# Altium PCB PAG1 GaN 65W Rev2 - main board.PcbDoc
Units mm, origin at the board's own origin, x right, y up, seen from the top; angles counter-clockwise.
Board outline 52 x 42 mm, 2 copper layers (Top Layer, Bottom Layer); 58 components, 37 nets, 153 pads, 55 vias.
Unrouted connection lines stored in the file: 1.
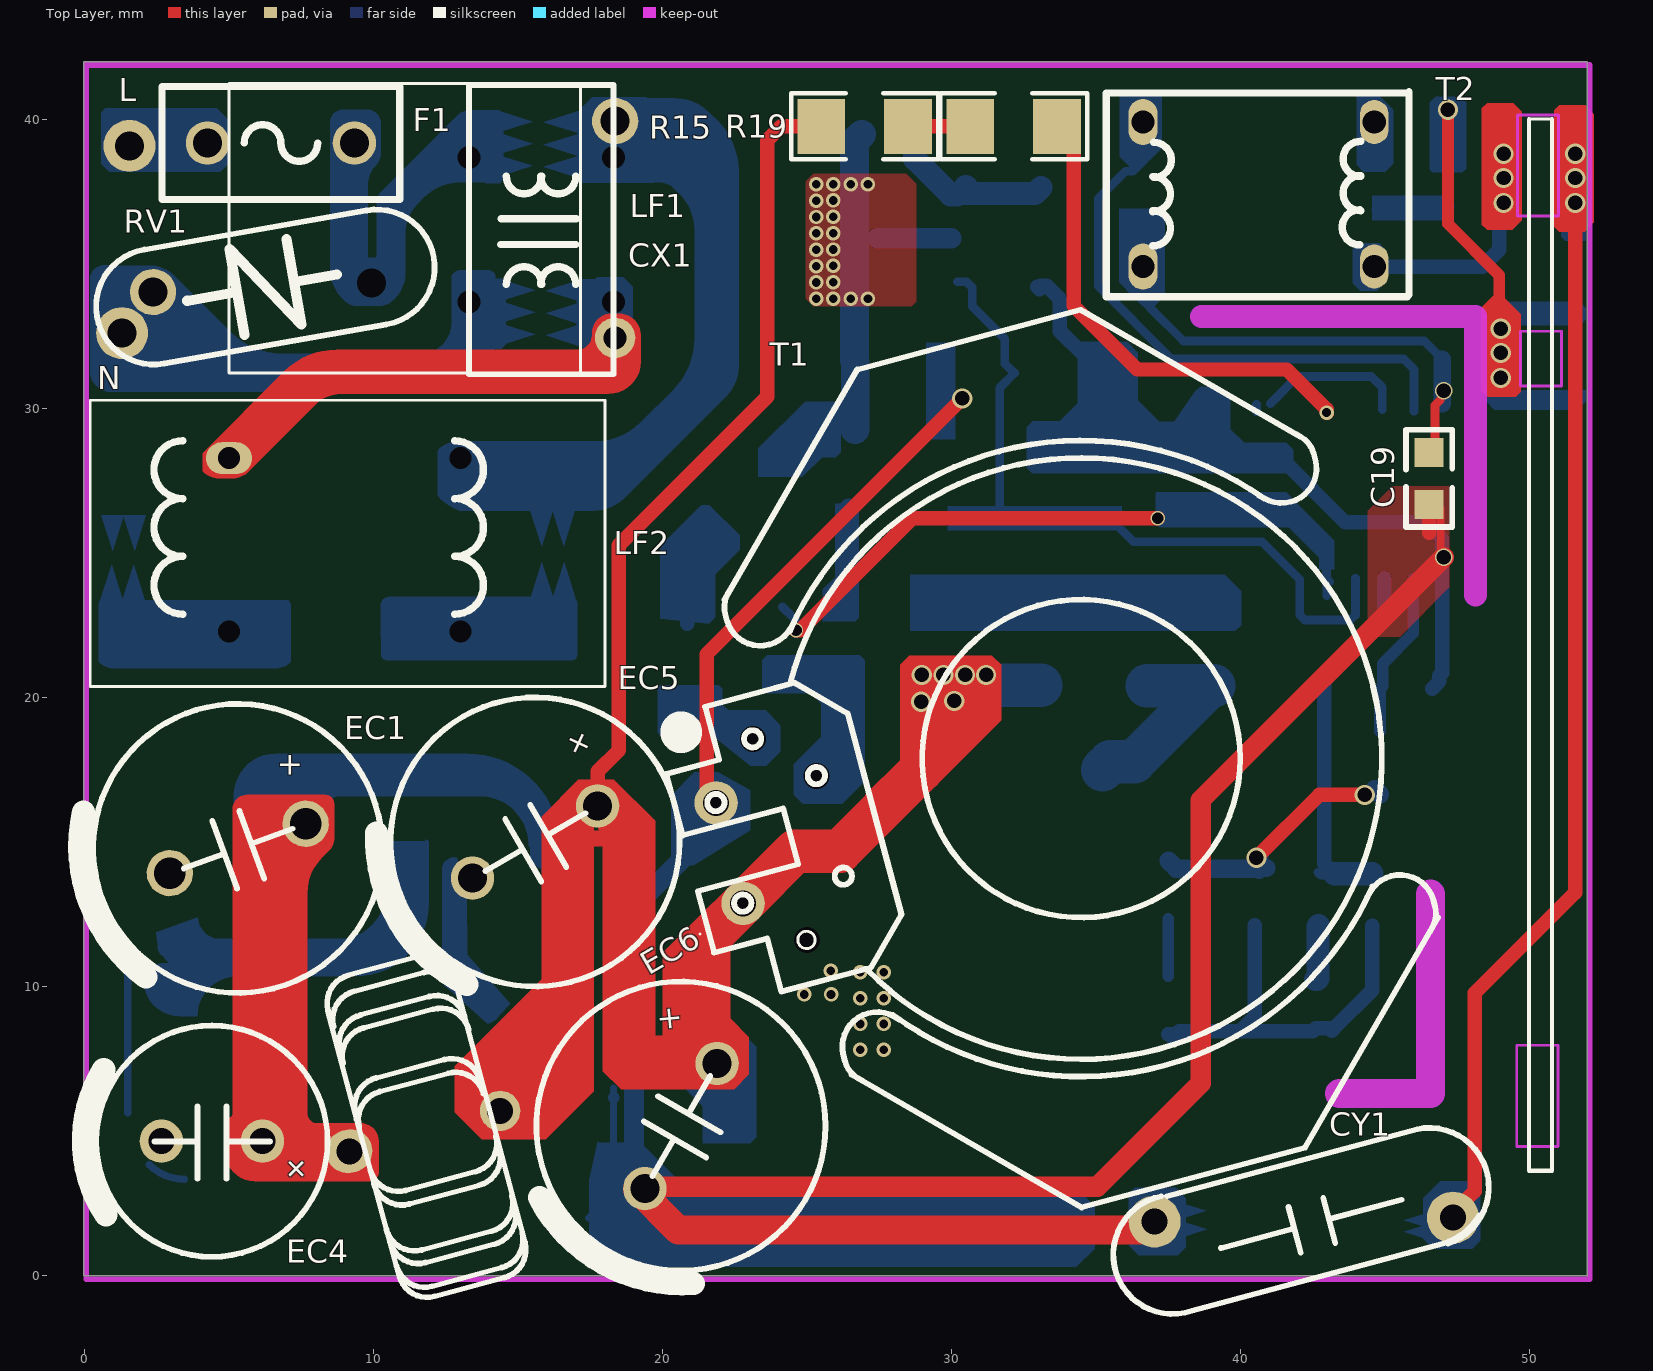
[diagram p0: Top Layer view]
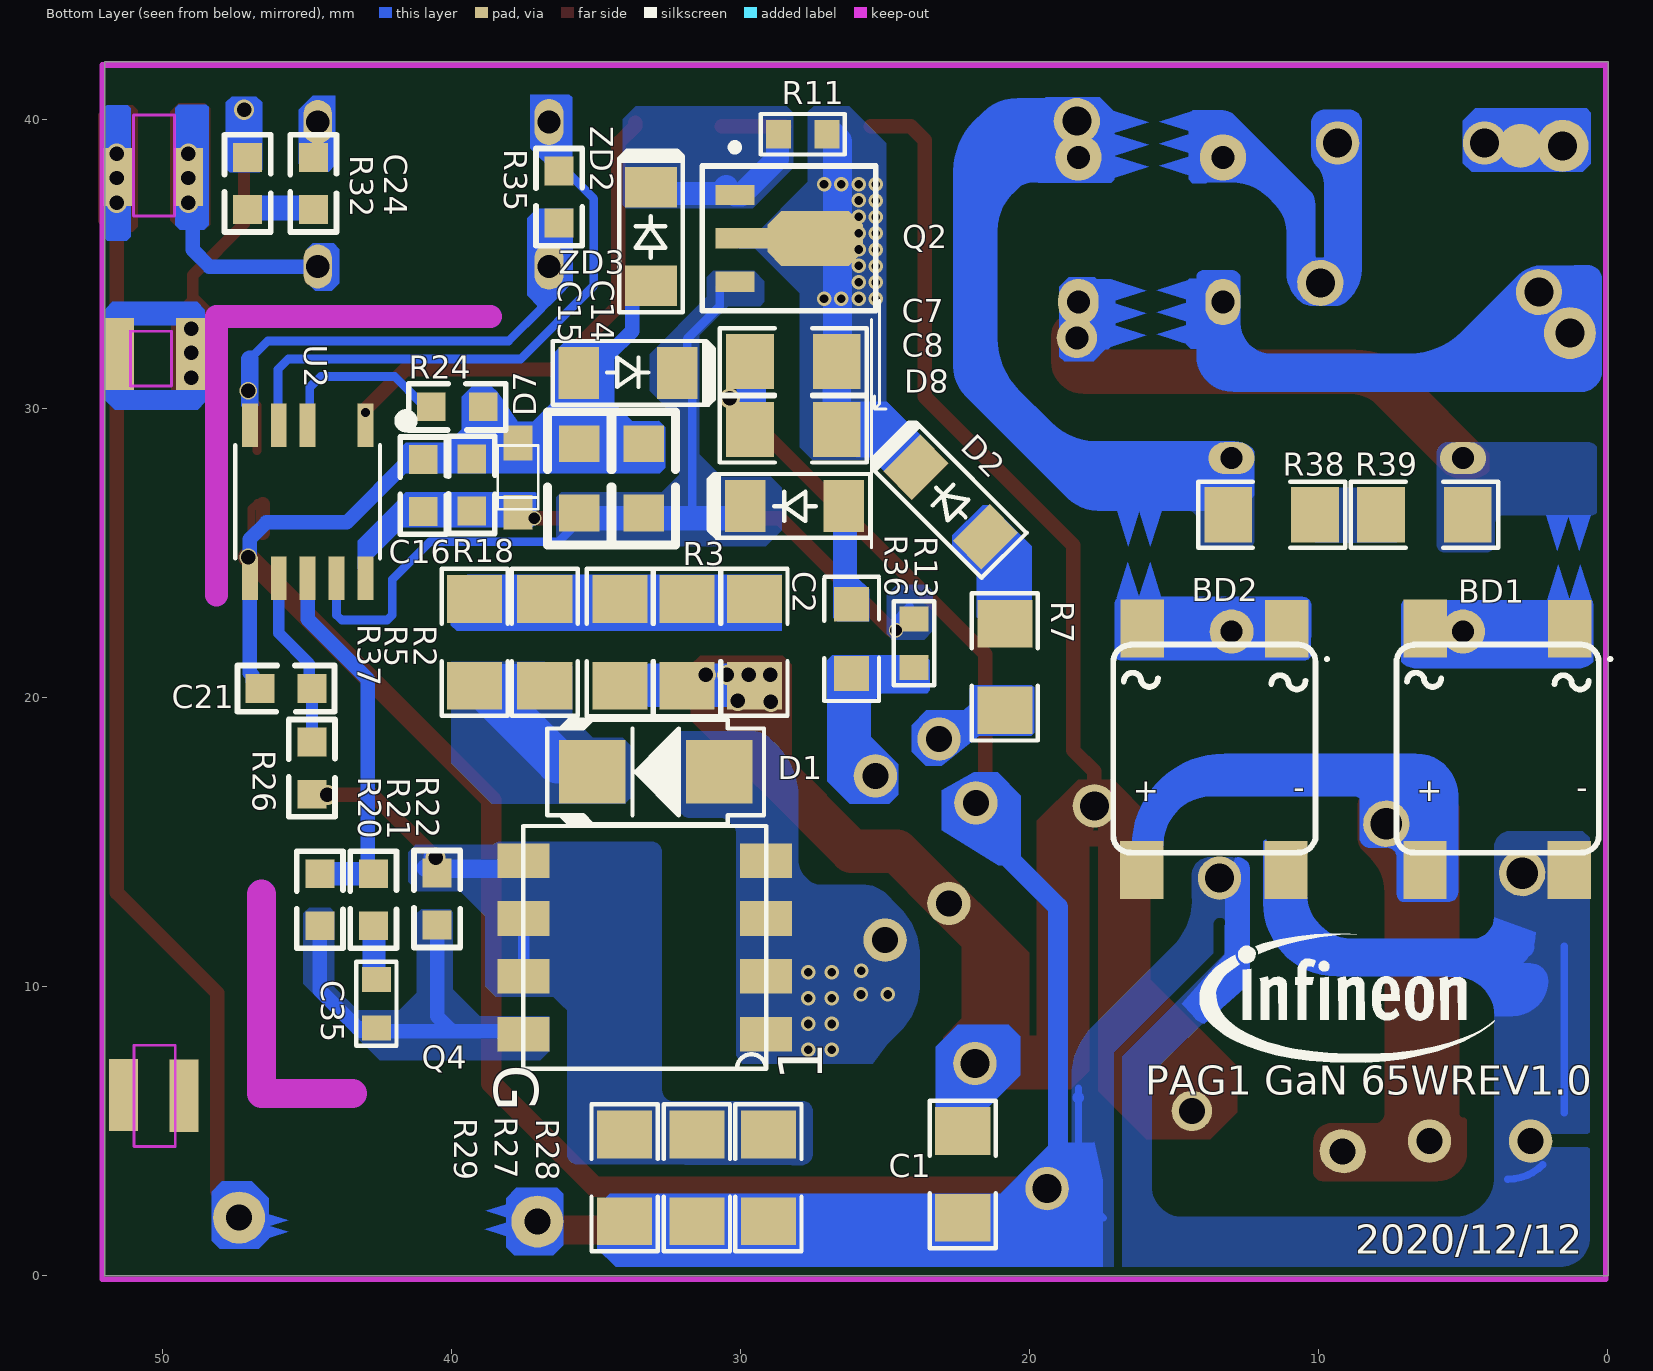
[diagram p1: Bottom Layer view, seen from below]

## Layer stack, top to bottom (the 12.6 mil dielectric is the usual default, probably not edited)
Top Solder: solder mask 0.0102, Solder Resist, Dk 3.5
Top Layer: signal copper 0.0356
Dielectric 1: dielectric 0.32, FR-4, Dk 4.8
Bottom Layer: signal copper 0.0356
Bottom Solder: solder mask 0.0102, Solder Resist, Dk 3.5

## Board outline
-0.02,-0.012 51.98,-0.012 51.98,41.988 -0.02,41.988

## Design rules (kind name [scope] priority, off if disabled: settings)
Clearance [All] p1: gap=0.254 ignorepadtopadclearanceinfootprint=FALSE except(0: Arc-Hole Track-Hole SMDPad-Hole THPad-Hole Via-Hole Fill-Hole Poly-Hole Region-Hole Text-Hole)
PolygonConnect [All] p1: connectstyle=Relief reliefconductorwidth=0.254 reliefentries=4 polygonreliefangle="90 Angle" airgapwidth=0.254
RoutingVias [All] p1: holewidth=0.711 width=1.27 viastyle="Through Hole" minholewidth=0.711 minwidth=1.27 maxholewidth=0.711 maxwidth=1.27
SolderMaskExpansion [All] p1: expansion=0.102 istentingtop=FALSE
Width [All] p1: maxlimit=0.254 minlimit=0.254 preferedwidth=0.254
30 further rules are at their usual default settings.

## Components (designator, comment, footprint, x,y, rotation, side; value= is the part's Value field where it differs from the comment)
BD1 "MSB407" BD(DB106) 3.813,18.223 r180 bottom
BD2 "MSB407" BD(DB106) 13.61,18.223 r180 bottom
C1 "103/500V 1206" R1206 22.313,4.998 r270 bottom
C2 "102/1KV 1206" R1206 29.52,20.398 r90 bottom
C7 "2.2UF 1206" R1206 26.67,31.617 r0 bottom
C8 "2.2UF 1206" r1206 26.667,29.265 r0 bottom
C14 "22UF/25V" WS0805 33.345,27.573 r90 bottom
C15 "22UF/25V" WS0805 35.577,27.573 r90 bottom
C16 "100PF" WS0603 40.97,27.323 r90 bottom
C19 "0.1UF" WS0603 46.52,27.573 r270 top
C21 "220PF" WS0603 45.72,20.298 r0 bottom
C24 "1nF  50V NPO" WS0603 44.77,37.773 r270 bottom
C35 "2.2nF/25V 0603" R0603 42.595,9.398 r270 bottom
CX1 "0.33uF" CX12.5 13.413,34.973 r270 top
CY1 "2200PF  400V" CAP10Y1 42.182,1.935 r15 top
D1 "GS2M  2A/1000V SMB" SMA 32.927,17.411 r0 bottom
D2 "DF1M" SOD-123/LL-34-T 22.72,26.748 r45 bottom
D7 "BAT54V2TA1G  SOD523" SOD-323-R 37.695,28.798 r270 bottom
D8 "DF1M" SOD-123/LL-34-T 28.12,26.623 r0 bottom
EC1 "33UF/400V" EC10#1 5.313,14.773 r200 top
EC4 "22UF400V" EC8-5_2 4.42,4.748 r180 top locked
EC5 "33UF400V" EC10#2 15.595,14.997 r210 top
EC6 "33UF400V" EC10#2 20.641,5.17 r240 top
F1 "T3.15A/250V" FUSE2 4.27,39.173 r0 top
LF1 "T9*3*3  600uH" T9*5*3 15.813,36.173 r270 top
LF2 "TD1212 15mH" "TD15 20*11" 8.013,25.873 r180 top locked
Q2 "FCX495QTA  NPN SOT89" SOT89 28.807,35.873 r270 bottom
Q4 "" DFN8*8_IGLD60R190D1 33.311,11.348 r90 bottom
R2 "390K 1206" R1206 34.17,23.398 r270 bottom
R3 "390K 1206" R1206 31.844,23.398 r270 bottom
R5 "10R/1206" R1206 36.77,20.398 r90 bottom
R7 "2.2R/1206" R1206 20.857,19.548 r90 bottom
R11 "200K" r0603 27.845,39.473 r0 bottom
R13 "7.5K" R0603 23.995,21.873 r90 bottom
R15 "47R 1206" R1206 25.495,39.748 r0 top
R18 "3k" WS0603 39.295,27.348 r90 bottom
R19 "47R 1206" R1206 30.645,39.748 r0 top
R20 "1K 0603" WS0603 44.545,12.998 r90 bottom
R21 "15R 0603" WS0603 42.695,12.998 r90 bottom
R22 "47K" WS0603 40.495,13.023 r270 bottom
R24 "499K" WS0603 39.795,30.048 r180 bottom
R26 "1K" WS0603 44.82,17.548 r270 bottom
R27 "0.43R 1206" r1206 31.509,1.881 r90 bottom
R28 "0.43R 1206" R1206 29.034,1.881 r90 bottom
R29 "0.43R 1206" R1206 34.009,1.881 r90 bottom
R32 "150R" WS0603 47.045,37.773 r270 bottom
R35 "2K" WS0603 36.27,37.298 r270 bottom
R36 "2.2R/0805" R0805 26.157,20.823 r90 bottom
R37 "10R/1206" R1206 39.195,20.398 r90 bottom
R38 "1.5M 1206" R1206 13.128,26.314 r180 bottom
R39 "1.5M 1206" R1206 7.845,26.314 r180 bottom
RV1 "10D561" MOV10D471 6.313,34.198 r10 top
T1 "RM10" RM10-3 34.495,17.873 r195 top locked
T2 "JQH LCL00T5138A1 3:9, 8mm" "Pulse Transformer" 40.62,37.398 r180 top
U2 "CYPAP112A3 SOIC10" SO-10 44.92,26.823 r270 bottom
ZD2 "16V" SOD-123/LL-34-T 33.095,35.923 r90 bottom
ZD3 "16V" SOD-123/LL-34-T 33.895,31.223 r180 bottom
? "T10" T11 11.78,4.998 r15 top

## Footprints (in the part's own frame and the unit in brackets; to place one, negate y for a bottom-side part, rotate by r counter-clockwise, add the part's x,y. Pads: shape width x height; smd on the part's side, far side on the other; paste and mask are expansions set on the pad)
BD(DB106) [mm]
  rect 1.5x2 smd: 1(2.48,-4.2) 2(2.5,4.15) 3(-2.5,4.16) 4(-2.51,-4.2)
  silkscreen extent -3.5,-3.6 3.9,3.6
CAP10Y1 [mm]
  round 1.8 hole 0.9: 1(-5,1.27) 2(5,-1.27)
  silkscreen extent -6.74,-2.09 6.54,2.06
CX12.5 [mm]
  round 1.6 hole 1: 1(-4.953,4.953)
  round 1.4 hole 0.8: 2(2.54,4.953)
  silkscreen extent -6.25,-8.4 3.75,3.75
DFN8*8_IGLD60R190D1 [mm]
  rect 1.2x1.8 smd: 1(-3,-4.191) 2(-1,-4.191) 3(1,-4.191) 4(3,-4.191) 5(3,4.191) 6(1,4.191) 7(-1,4.191) 8(-3,4.191)
  silkscreen extent -4.2,-4.2 4.2,4.2
EC8-5_2 [mm]
  round 1.5 hole 0.9: 1(-1.75,0.1) 2(1.75,0.1)
  silkscreen extent -4,-3.9 4.44,4.1
EC10#1 [mm]
  round 1.6 hole 1.1: 1(-2.5,0) 1(2.5,0)
  silkscreen extent -5,-5 5.44,5
EC10#2 [mm]
  round 1.5 hole 1: 1(-2.5,0) 2(2.5,0)
  silkscreen extent -5,-5 5.44,5
FUSE2 [mm]
  round 1.5 hole 1: 1(-0.005,-0.002) 2(5.075,-0.002)
  silkscreen extent -1.58,-1.96 6.65,1.95
MOV10D471 [mm]
  round 0 / inner round 0 / far side round 1.6 hole 1: 1(3.6,-0.5)
  round 1.6 hole 1: 2(-3.9,0.5)
  silkscreen extent -5.96,-2 5.87,2
"Pulse Transformer" [mm]
  oval 1x1.524 hole 0.8: 1(-4,-2.5) 2(-4,2.5)
  oval 1x1.6 hole 0.8: 3(4,-2.5) 4(4,2.5)
  silkscreen extent -5.2,-3.55 5.26,3.54
R0603 [mm]
  rect 0.87x1 smd: 1(-0.838,0) 2(0.84,0)
  silkscreen extent -1.45,-0.7 1.45,0.7
r0603 [mm]
  rect 0.87x1 smd: 1(-0.838,0) 2(0.84,0)
  silkscreen extent -1.45,-0.7 1.45,0.7
R0805 [mm]
  rect 1.2x1.2 smd: 1(0,0) 2(2.4,0)
  silkscreen extent -0.95,-0.95 3.35,0.95
R1206 [mil]
  rect 65x75 smd: 1(0,0) 2(118.11,0)
  silkscreen extent -41,-45 159,45
r1206 [mil]
  rect 65x75 smd: 1(0,0) 2(118.11,0)
  silkscreen extent -41,-45 159,45
RM10-3 [mm]
  round 1.5 hole 0.9: 1(12.6,-1.8) 6(12.6,1.8)
  round 0 / inner round 0 / far side round 1.5 hole 0.9: 2(10.8,-3.6) 3(9,-1.8) 5(10.8,3.6)
  silkscreen extent -10.49,-15.01 14.01,14.99
SMA [mm]
  rect 2.3x2.2 smd: A(-2.192,-0.009) K(2.208,-0.009)
  silkscreen extent -3.74,-1.81 3.76,1.79
SO-10 [mm]
  rect 1.5x0.55 smd: 1(-2.59,1.95) 3(-2.59,-0.05) 4(-2.59,-1.05) 5(-2.59,-2.05) 6(2.71,-2.05) 7(2.71,-1.05) 8(2.71,-0.05) 9(2.71,0.95) 10(2.71,1.95)
  silkscreen extent -2.94,-2.55 2.01,3.55
SOD-123/LL-34-T [mm]
  rect 1.4x1.8 smd: 1(-1.69,0) 2(1.71,0)
  silkscreen extent -2.6,-1.1 2.98,1.1, body extent -1.85,-0.81 1.85,0.79, height 1.2
SOD-323-R [mm]
  rect 1.2x1 smd: 1(0,0) 2(2.393,0)
  silkscreen extent 0.09,-0.7 2.29,0.7
SOT89 [mm]
  rect 0.7x1.35 smd: 1(-1.5,-1.388) 3(1.5,-1.388)
  rect 0.7x1.8 smd: 2(0,-1.162)
  oct 1.9x3.3 smd: 2(0,1.388)
  silkscreen extent -3.27,-2.51 2.5,3.49, body extent -2.2,-1.97 2.3,1.97, height 1.4
T9*5*3 [mm]
  round 0 / inner round 0 / far side round 1.6 hole 0.8: 1(-2.5,-2.5) 2(-2.5,2.5)
  round 0 / inner round 0 / far side oval 1.6x1.4 hole 0.8: 3(2.5,2.5)
  round 0 / inner round 0 / far side oval 1.6x1.2 hole 0.8: 4(2.5,-2.5)
  silkscreen extent -5,-2.5 5,2.5
T11 [mm]
  oval 1.6x1.5 hole 0.9: 1(-2.7,0)
  round 1.4 hole 0.9: 2(2.7,0)
  silkscreen extent -2.18,-5.61 2.39,5.89
"TD15 20*11" [mm]
  round 0 / inner round 0 / far side oval 1.6x1.1 hole 0.762: 1(-5,-2.4)
  round 0 / inner round 0 / far side round 1.524 hole 0.762: 2(-5,3.6) 3(3,3.6)
  oval 1.6x1.1 hole 0.762: 4(3,-2.4)
  silkscreen extent -10,-4.4 7.8,5.5
WS0603 [mm]
  rect 1x1 smd: 1(-0.9,0) 2(0.9,0)
  silkscreen extent -1.68,-0.8 1.68,0.8, body extent -1.78,-0.9 1.78,0.9, height 1.27
WS0805 [mm]
  rect 1.27x1.397 smd: 1(-1.2,0) 2(1.2,0)
  silkscreen extent -2.3,-1.1 2.3,1.1, body extent -2.45,-1.25 2.45,1.25, height 0.4

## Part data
BD1 BD2: library part BR805D_1
C1 C2 C7 C8 C14 C15 C16 C19 C21 C24 C35 CX1: library part CAP1, "电容"
CY1: library part 0_0.01uF-50V-10%-X7R-0603
D1 D2 D7 D8: library part DIODE, "二极管"
EC1 EC4 EC5 EC6: library part CAP2, "电解电容"
F1: library part FUSE1
LF1 LF2: library part "INDUCTOR IRON_8"
Q2: library part NPN
Q4: library part IGT60R190D1S, "Cool GaN PG-LSON-8"
R2 R3 R5 R7 R11 R13 R15 R18 R19 R20 R21 R22 R24 R26 R27 R28 R29 R32 R35 R36 R37 R38 R39: library part RES2, "电阻"
RV1: library part VARISTOR
T1: library part PA5222NL_24
T2: library part TRANSFORMER_11
U2: library part PAG1P_3
ZD2 ZD3: library part ZD1
?: library part INDUCTOR, "电感"

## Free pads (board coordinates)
  rect 1x2.5 smd far side: 0(49.02,31.873) 0(49.245,6.223) 0(51.345,6.248) 0(51.47,31.873)
  rect 1x2 smd far side: 0(49.095,37.998) 0(51.545,37.998)
  round 1.524 smd far side: 1(3.02,39.073)
  round 1.8 hole 1: L(1.57,39.073) N(1.313,32.598)

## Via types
v1: diameter 0.5, hole 0.3, Top Layer to Bottom Layer, 32 vias
v2: diameter 0.7, hole 0.5, Top Layer to Bottom Layer, 19 vias
v3: diameter 0.5, hole 0.4, Top Layer to Bottom Layer, 2 vias
v4: diameter 0.6, hole 0.5, Top Layer to Bottom Layer, 2 vias

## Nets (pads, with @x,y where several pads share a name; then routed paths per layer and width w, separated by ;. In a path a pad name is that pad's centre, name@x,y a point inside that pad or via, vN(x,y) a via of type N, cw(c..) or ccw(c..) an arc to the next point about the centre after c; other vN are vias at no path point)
GND: BD1.1 BD2.1 C1.2 C7.2 C8.2 C14.2 C15.2 C16.2 C19.2 C21.2 CY1.1 D7.1 EC1.1@2.964,13.918 EC4.2 EC5.2 EC6.2 R18.2 R24.2 R27.1 R28.1 R29.1 T1.1 U2.6 ZD2.1 ZD3.1 | length 154.7
  Top Layer w0.254: EC6.2@18.87,2.998 EC6.2@18.905,3.333 ; C19.2@46.72,26.723 46.92,26.523 v4@46.92,24.848
  Top Layer w0.5: EC5.2@13.348,13.523 EC5.2@13.545,13.72 ; T1.1 21.531,16.678 21.531,21.497 v2(30.37,30.336)
  Top Layer w0.508: 46.52,25.698 C19.2 ; v4@46.92,24.848 v4(47.02,24.848)
  Top Layer w0.7: EC6.2@19.27,3.198 19.4,3.068 35.04,3.068 38.62,6.648 38.62,16.448 v4(47.02,24.848)
  Top Layer w1: EC6.2@19.13,2.998 20.555,1.573 CY1.1@36.516,1.573
  Bottom Layer w0.254: 1.513,5.628 1.513,11.384 ; 2.257,3.832 ccw(c3.462,5.036) 3.462,3.333 ; BD2.1@10.933,13.973 11.13,13.776 BD2.1@11.558,13.348 ; EC5.2@13.305,13.348 EC5.2@13.348,13.523 ; 17.454,1.992 EC6.2@18.795,3.333 ; 18.31,4.223 18.31,6.148 18.31,6.487 ; EC6.2@18.97,2.998 20.045,2.998 19.02,4.023 ; C1.2@22.77,2.198 33.02,2.198
  Bottom Layer w0.4: 18.31,6.148 18.32,6.158
  Bottom Layer w0.5: 2.795,11.348 ccw(c2.895,11.348) 2.895,11.248 8.59,11.248 ccw(c8.59,13.788) 11.13,13.776 ccw(c8.59,13.788) 11.13,13.788 BD2.1 ; C14.2@33.302,28.448 35.577,28.448 D7.1@37.545,28.448 ; D7.1@37.708,28.61 38.07,28.248 R18.2@39.445,28.248 ; R24.2@39.37,30.073 39.37,28.323 R18.2@39.445,28.248 ; C21.2 46.87,20.548 46.87,20.741 46.97,20.841 U2.6 46.97,24.848 46.97,25.473 46.395,26.048 43.62,26.048 41.42,28.248 40.97,28.248 R18.2@39.445,28.248
  Bottom Layer w0.508: ZD2.1@32.965,34.203 33.045,34.123 33.045,34.183 ZD2.1 33.295,34.233 33.741,33.787 33.741,32.669 34.548,31.862
  Bottom Layer w0.7: 19.02,4.023 19.02,12.748 21.527,15.255
Net_1: ?.1 BD1.4 BD2.4 EC1.1@7.662,15.628 EC4.1 | length 15
  Bottom Layer w0.25: BD2.4@15.923,13.973 BD2.4@15.923,14.557 ; BD1.4 6.323,14.335 BD1.4
  Bottom Layer w1: BD1.4 6.323,15.149 cw(c8.863,15.149) 7.067,16.945 cw(c8.402,15.61) 8.402,17.498 13.18,17.498 cw(c13.18,15.108) 14.87,16.798 15.179,16.489 cw(c13.383,14.693) 15.923,14.693 BD2.4@15.923,14.557
NetBD1_2: BD1.2 BD1.3 LF2.3
NetBD2_2: BD2.2 BD2.3 LF2.2
NetC2_2: C2.2 R2.1 R3.1 R5.2 R37.2
NetC7_1: C7.1 C8.1 D2.2 Q2.2 R11.1 | length 12.9
  Bottom Layer w0.7: Q2.2@27.42,35.873 Q2.2@29.995,35.873
  Bottom Layer w1: C8.1 26.67,29.267 C7.1 26.645,31.642 26.645,39.223 R11.1@26.895,39.473
  other v1: 25.318,33.782 25.914,33.782 26.511,33.782 27.108,33.782 25.318,34.348 25.914,34.355 25.318,34.914 25.914,34.921 25.318,35.48 25.914,35.487 25.318,36.046 25.914,36.053 25.318,36.612 25.914,36.62 25.318,37.178 25.914,37.186 25.318,37.744 25.914,37.744 26.511,37.744 27.108,37.744
NetC14_1: C14.1 C15.1 D8.2 Q2.3 U2.9 ZD3.2 | length 21.4
  Bottom Layer w0.3: Q2.3 30.52,34.373 30.72,34.173 30.72,33.523 31.845,32.398 31.845,31.548 ZD3.2@32.095,31.298 ; 31.595,26.198 31.595,26.373 31.67,26.373 31.67,30.708 ZD3.2@32.177,31.215 ; C15.1@35.477,26.198 36.295,25.38 40.738,25.38 42.045,24.073 42.045,22.849 42.221,22.673 43.794,22.673 43.97,22.849 U2.9
NetC16_1: C16.1 D7.2 R13.2 R18.1 U2.10 | length 21.5
  Top Layer w0.5: v3(24.62,22.323) 24.77,22.323 28.645,26.198 v3(37.132,26.198)
  Bottom Layer w0.3: R13.2@24.145,23.135 24.57,22.71 ; v3(24.62,22.323) 24.62,22.66 24.57,22.71 ; D7.2@37.545,26.055 D7.2@37.813,26.323 ; C16.1@41.145,26.448 41.745,26.448 42.97,25.223 U2.10 ; U2.10@43.02,24.048 U2.10@43.02,24.038 ; R13.2@24.313,22.966 24.57,22.71 ; R13.2@24.313,22.966 24.57,22.71 ; R13.2@24.313,22.966 24.57,22.71 ; U2.10 43.07,23.998 U2.10@42.982,23.998 ; U2.10 42.972,23.996 42.982,23.523 U2.10@42.982,23.998 ; U2.10 U2.10@43.02,24.038 ; U2.10@42.982,23.998 43.02,24.035 U2.10@43.02,24.038
NetC19_1: C19.1 R35.2 T2.4 U2.5 | length 17.4
  Top Layer w0.3: C19.1@46.72,28.523 46.72,30.098 46.895,30.273
  Bottom Layer w0.3: R35.2 36.27,35.748 36.895,35.123 36.895,33.448 38.02,32.323 46.345,32.323 46.97,31.698
  Bottom Layer w0.6: U2.5@46.97,30.148 46.97,31.698
  other v4: 47.02,30.598
NetC21_1: C21.1 R26.1 U2.7 | length 5.8
  Bottom Layer w0.4: R26.1@44.82,18.819 C21.1 44.911,20.389 44.911,21.164 45.97,22.223 U2.7
NetC24_1: C24.1 T2.1 | length 1
  Bottom Layer w0.3: C24.1@44.62,38.898 T2.1
NetC24_2: C24.2 R32.2 | length 2.4
  Bottom Layer w0.5: C24.2 R32.2 R32.2@47.145,36.973
NetC35_1: C35.1 R21.1 | length 1.9
  Bottom Layer w0.8: C35.1 42.635,10.236 42.67,10.271 42.67,12.073 R21.1
NetC35_2: C35.2 Q4.8 R20.1 R22.2 | length 14
  Bottom Layer w0.5: Q4.8 Q4.8@37.77,8.348 ; Q4.8@37.645,8.223 Q4.8@37.77,8.348 ; 40.045,8.523 40.495,8.973 R22.2 ; 43.145,8.473 43.23,8.558 ; R20.1 44.545,9.873 43.23,8.558 ; Q4.8@37.77,8.348 37.875,8.453 42.49,8.453 C35.2 43.23,8.558
NetCX1_1: CX1.1 LF1.2 LF2.1 R38.1 | length 6.2
  Bottom Layer w1.5: 19.47,39.587 21.114,37.943 cw(c19.318,36.147) 21.858,36.147 21.858,34.256
NetCX1_2: CX1.2 LF1.3 LF2.4 R39.2
NetD1_A: D1.A Q4.1 Q4.2 Q4.3 Q4.4 T1.5
  other v1: 26.845,7.81 27.653,7.81 26.845,8.703 27.653,8.703 26.845,9.595 27.653,9.595 24.901,9.723 25.833,9.723 26.845,10.487 27.653,10.487 25.82,10.548
NetD1_K: D1.K R5.1 R37.1 | length 7.2
  Bottom Layer w1.5: D1.K@35.22,17.498 35.491,17.769 36.314,17.769 R37.1@38.943,20.398 ; R5.1 R37.1@38.943,20.398 ; R37.1@39.07,20.398 38.945,20.398 R37.1@38.943,20.398
NetD2_1: D2.1 R7.2 | length 2.8
  Bottom Layer w0.5: R7.2 20.857,23.775 D2.1@21.991,24.908
NetD3_2: 
NetD8_1: D8.1 R36.2 | length 3.5
  Bottom Layer w0.5: R36.2 26.245,23.31 26.245,26.438 D8.1
NetF1_1: F1.1 pad.1 pad.L | length 2.7
  Bottom Layer w0.3: pad.L 4.168,39.073 F1.1
NetF1_2: F1.2 LF1.1 RV1.1
NetGPIO1_1: R32.1 | length 10.2
  Top Layer w0.3: v2@49.195,31.91 v2@49.195,31.923
  Top Layer w0.4: v2(47.17,40.323) 47.17,36.373 48.945,34.598 48.945,31.098 v2(48.995,31.048)
  Bottom Layer w0.5: v2@48.97,31.923 48.945,31.923 v2@49.02,31.873
  other v2: 48.995,31.91 48.995,32.748
NetLF1_4: LF1.4 pad.N RV1.2
NetQ2_1: Q2.1 R11.2 ZD2.2 | length 5.6
  Bottom Layer w0.8: R11.2@28.695,39.498 28.72,39.473 28.72,38.623 29.97,37.373 Q2.1 ; Q2.1@30.47,37.423 32.885,37.423 ZD2.2 ; Q2.1@30.49,37.668 Q2.1@30.525,37.633
NetQ4_5: Q4.5 Q4.6 Q4.7 R22.1 R26.2 R27.2 R28.2 R29.2 | length 11
  Top Layer w0.5: v2(40.545,14.448) 42.72,16.623 44.27,16.623 v2@44.295,16.648
  Bottom Layer w0.4: Q4.7 Q4.6
  Bottom Layer w0.5: R22.1@40.645,13.973 40.72,14.048 40.72,14.098 v2@40.72,14.498
  Bottom Layer w0.635: Q4.5 37.777,14.073 R22.1@40.67,14.073 ; R22.1@40.67,14.098 40.72,14.098 R22.1@40.895,14.098 ; R26.2@44.638,16.83 R26.2
  other v2: 44.295,16.623
NetR7_1: R7.1 T1.2
NetR13_1: R13.1 R36.1 T1.3
NetR15_2: R15.2 R19.1 | length 2.2
  Top Layer w0.508: R15.2 R19.1
NetR19_2: R19.2 U2.1 | length 16.9
  Top Layer w0.5: R19.2@33.645,39.875 R19.2 34.22,39.173 34.22,36.823 34.22,33.537 36.42,31.337 41.596,31.337 42.97,29.963 v1(42.97,29.848)
NetR20_2: R20.2 R21.2 U2.8 | length 12.8
  Bottom Layer w0.305: R21.2@42.67,13.948 42.695,13.923 42.77,13.848 R21.2@42.87,13.848
  Bottom Layer w0.5: 43.245,13.898 42.895,14.248 42.895,20.623 44.97,22.698 U2.8
  Bottom Layer w0.8: 43.245,13.898 R20.2
NetR24_1: R24.1 U2.3 | length 5.5
  Bottom Layer w0.3: R24.1@40.545,29.873 R24.1@40.545,30.132 ; R24.1@41.02,30.157 41.961,31.098 44.52,31.098 44.895,30.723 U2.3@44.895,29.948
NetR35_1: R35.1 T2.3 U2.4 | length 20.2
  Bottom Layer w0.3: 37.12,39.898 37.12,39.048 R35.1 36.02,38.198 35.07,37.248 35.07,34.231 37.603,31.698 45.645,31.698 45.995,31.348 U2.4@45.995,29.898
NetR38_2: R38.2 R39.1
SR_VSS: CY1.2 pad.0@49.095,37.998 pad.0@51.545,37.998 T2.2 | length 45.9
  Top Layer w0.3: v2@49.295,37.96 v2@49.295,37.973 ; v2(51.57,37.098) v2(51.57,37.96) 51.57,38.598 v2@51.67,38.698 ; v2(51.57,38.798) 51.779,38.798 v2@51.779,38.796 ; v2@51.77,37.96 v2@51.77,37.973
  Top Layer w0.5: CY1.2@47.225,1.961 47.225,2.053 48.095,2.923 48.095,9.773 51.57,13.248 v2(51.57,37.098)
  Bottom Layer w0.5: T2.2@44.37,34.898 48.37,34.898 48.945,35.473 pad.0@48.945,37.643 ; pad.0@49.045,37.973 pad.0@49.07,37.973 ; pad.0@51.545,37.973 51.52,37.973 pad.0@51.545,37.998
  other v2: 49.095,37.098 49.095,37.96 49.095,38.798
"VDC IN": ?.2 C1.1 C2.1 EC5.1 EC6.1 R2.2 R3.2 R15.1 T1.6 | length 48.3
  Top Layer w0.5: EC5.1 17.76,17.436 18.485,18.161 18.485,25.263 23.62,30.398 23.62,39.262 24.106,39.748 R15.1
  Top Layer w1.5: EC6.1@21.405,7.663 21.405,11.488 T1.6 24.59,14.673 26.145,14.673 28.97,17.498 v2@28.97,20.673
  Bottom Layer w1.5: C2.1@29.37,20.414 29.72,20.414 33.095,20.414
  other v2: 28.945,19.848 30.095,19.873 28.97,20.773 29.72,20.773 30.47,20.773 31.195,20.773

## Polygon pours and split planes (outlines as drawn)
no net on Bottom Solder "NONET_L-01_P-001" (solid): 30.164,7.515 cw(c29.551,8.128) 29.551,7.261 25.592,7.261 cw(c25.592,7.568) 25.375,7.351 24.195,8.531 cw(c25.115,9.451) 23.814,9.451 23.814,11.833 cw(c24.734,11.833) 24.083,12.483 25.084,13.484 cw(c25.391,13.177) 25.391,13.611 27.497,13.611 27.825,13.939 ccw(c27.392,14.373) 28.005,14.373 28.005,15.336 cw(c28.439,15.336) 28.132,15.643 28.333,15.844 cw(c28.767,15.411) 28.767,16.024 29.678,16.024 cw(c29.678,15.157) 30.291,15.77 cw(c29.984,15.463) 30.418,15.463 30.418,8.128 cw(c29.551,8.128)
no net on Bottom Solder "NONET_L-01_P-001" (solid): 13.245,37.723 13.245,40.548 17.945,40.548 17.945,37.723
no net on Bottom Solder "NONET_L-01_P-001" (solid): 13.42,32.048 13.42,34.798 18.195,34.798 18.195,32.048
no net on Bottom Solder "NONET_L-01_P-001" (solid): 0.37,23.548 0.37,26.498 2.295,26.498 2.295,23.523
no net on Bottom Solder "NONET_L-01_P-001" (solid): 37.342,0.869 37.342,2.548 47.141,2.548 47.141,0.928
no net on Bottom Solder "NONET_L-01_P-001" (solid): 15.167,23.573 15.167,26.573 17.067,26.573 17.067,23.573
no net on Bottom Solder (solid): 19.907,21.717 19.907,25.222 21.381,26.695 21.635,26.695 22.701,25.629 22.701,25.07 21.863,24.232 21.863,21.717
no net on Bottom Solder (solid): 27.477,40.462 27.705,40.234 27.705,37.846 28.67,36.881 28.67,34.595 28.01,33.934 28.01,28.626 27.527,28.143 25.495,28.143 24.175,26.822 23.946,26.822 22.803,27.965 22.803,28.143 24.911,30.251 24.911,39.167 26.207,40.462
no net on Top Solder (solid): 25.013,38.075 24.759,37.821 24.759,33.579 25.013,33.325 28.493,33.325 28.747,33.579 28.747,37.795 28.467,38.075
NetCX1_1 on Bottom Layer "NETCX1_1_L02_P014" (solid, pour order 14): 12.226,27.074 12.226,25.411 ccw(c12.44,25.411) 12.44,25.197 14.04,25.197 ccw(c14.04,25.375) 14.218,25.375 14.218,26.179 cw(c14.487,26.179) 14.487,26.448 ccw(c14.487,26.56) 14.599,26.56 14.599,27.051
NetCX1_2 on Bottom Layer "NETCX1_2_L02_P013" (solid, pour order 13): 5.912,26.543 5.912,25.273 cw(c5.658,25.273) 5.658,25.019 4.185,25.019 cw(c4.185,25.298) 3.905,25.298 3.905,26.035 ccw(c3.651,26.035) 3.651,26.289 cw(c3.651,26.416) 3.524,26.416 3.524,26.543
NetR38_2 on Bottom Layer "NETR38_2_L02_P012" (solid, pour order 12): 7.309,27.254 7.309,25.349 10.128,25.349 10.128,27.254
NetCX1_2 on Bottom Layer "NETCX1_2_L02_P011" (solid, pour order 11): 0.324,28.448 cw(c0.705,28.448) 0.705,28.829 5.531,28.829 cw(c5.531,28.448) 5.912,28.448 5.912,26.543 cw(c5.658,26.543) 5.658,26.289 0.578,26.289 cw(c0.578,26.543) 0.324,26.543
NetC35_2 on Bottom Layer "NETC35_2_L02_P010" (solid, remove dead copper, pour order 10): 39.02,8.973 39.945,9.898 39.945,12.573 40.045,12.673 41.045,12.673 41.195,12.523 41.195,9.773 41.795,9.173 43.245,9.173 44.045,9.973 44.045,12.573 44.195,12.723 44.92,12.723 45.12,12.523 45.12,10.098 42.47,7.448 36.92,7.448 36.595,7.773 36.62,7.798 36.62,8.973
NetQ4_5 on Bottom Layer "NETQ4_5_L02_P009" (solid, remove dead copper, pour order 9): 37.02,14.948 37.07,14.898 41.27,14.898 41.27,14.873 41.495,14.648 41.495,13.623 41.17,13.298 39.695,13.298 38.82,12.423 38.82,9.998 38.47,9.648 36.47,9.648 35.72,8.898 33.62,8.898 32.845,9.673 32.845,14.423 33.395,14.973
NetC16_1 on Bottom Layer "NETC16_1_L02_P007" (solid, remove dead copper, pour order 7): 24.595,23.898 24.945,23.548 24.945,22.198 24.745,21.998 23.645,21.998 23.345,22.298 23.345,23.673 23.57,23.898
NetC14_1 on Bottom Layer "NETC14_1_L02_P006" (solid, remove dead copper, pour order 6): 30.945,34.748 31.17,34.523 31.17,33.848 33.145,31.873 33.145,30.598 32.12,29.573 32.12,27.698 32.72,27.098 36.195,27.098 36.37,26.923 36.37,25.248 36.345,25.223 29.12,25.223 28.57,25.773 28.57,27.248 28.945,27.623 30.645,27.623 31.42,28.398 31.42,32.523 30.42,33.523 29.32,33.523 29.17,33.673 29.17,34.398 29.52,34.748
NetC7_1 on Bottom Layer "NETC7_1_L02_P005" (solid, remove dead copper, pour order 5): 27.47,40.448 27.67,40.248 27.67,37.823 29.545,35.948 29.545,35.573 27.945,33.973 27.945,28.648 27.52,28.223 24.645,28.223 24.22,28.648 24.22,29.498 24.962,30.24 24.962,39.165 26.245,40.448
NetQ2_1 on Bottom Layer "NETQ2_1_L02_P004" (solid, remove dead copper, pour order 4): 33.62,40.448 34.07,39.998 34.07,37.023 33.97,36.923 29.57,36.923 28.17,38.323 28.17,40.223 28.395,40.448
NetD1_K on Bottom Layer "NETD1_K_L02_P003" (solid, remove dead copper, pour order 3): 36.77,21.223 39.995,21.223 39.995,17.723 38.595,16.323 33.97,16.323 33.97,16.348 33.745,16.573 33.745,18.273 34.07,18.598 35.12,18.598 35.12,18.623 35.82,19.323 35.82,21.098 35.945,21.223
NetQ4_5 on Bottom Layer "NETQ4_5_L02_P002" (solid, pour order 2): 28.22,3.823 27.92,3.823 cw(c27.92,4.248) 27.495,4.248 27.495,5.673 cw(c27.845,5.673) 27.845,6.023 32.32,6.023 ccw(c32.32,6.423) 32.72,6.423 32.72,14.648 cw(c33.07,14.648) 33.07,14.998 38.345,14.998 cw(c38.345,14.723) 38.62,14.723 38.62,11.598 cw(c38.445,11.598) 38.445,11.423 36.17,11.423 ccw(c36.17,11.248) 35.995,11.248 35.995,4.198 cw(c35.645,4.198) 35.645,3.848
NetD1_A on Bottom Layer "NETD1_A_L02_P001" (solid, pour order 1): 24.934,7.978 24.539,8.373 cw(c26.335,10.169) 23.795,10.169 23.795,10.982 cw(c26.335,10.982) 24.539,12.778 24.934,13.173 cw(c25.779,12.328) 25.779,13.523 27.27,13.523 ccw(c27.27,14.042) 27.637,13.675 27.772,13.81 ccw(c27.214,14.369) 28.004,14.369 28.004,16.555 cw(c30.544,16.555) 28.748,18.351 28.97,18.573 cw(c29.565,17.978) 29.565,18.819 32.185,18.819 32.185,16.288 cw(c31.762,16.288) 32.061,15.989 31.97,15.898 cw(c31.819,16.049) 31.819,15.835 30.735,15.835 ccw(c30.734,15.339) 30.383,15.69 30.245,15.551 ccw(c30.486,15.31) 30.145,15.31 30.145,7.609 29.945,7.326 25.432,7.326
GND on Bottom Layer "Bottom Layer-No Net 1" (solid, pour order 0): 1.639,0.306 16.797,0.306 16.797,7.582 13.193,11.186 13.192,12.147 cw(c13.42,12.147) 13.649,12.147 13.649,11.156 17.092,7.712 17.092,0.306 18.109,0.306 ccw(c18.109,0.742) 18.545,0.742 18.545,6.851 ccw(c16.007,6.852) 17.801,8.647 14.919,11.53 cw(c16.603,12.982) 14.385,13.146 14.385,13.873 ccw(c13.765,13.841) 13.765,14.462 12.986,14.462 ccw(c13.009,13.958) 12.506,13.924 12.526,13.923 12.526,11.183 12.537,11.19 ccw(c15.02,11.19) 13.298,9.401 15.782,7.009 15.782,3.09 cw(c14.721,3.09) 14.721,2.029 5.306,2.029 cw(c5.306,3.411) 3.923,3.411 3.923,14.817 ccw(c3.381,14.817) 3.381,15.359 2.161,15.37 0.861,15.37 0.63,15.139 0.63,4.892 0.695,4.902 2.245,4.902 2.474,4.673 2.245,4.444 0.695,4.444 0.63,4.454 0.63,1.315 ccw(c1.639,1.315)
NetC7_1 on Top Layer "NETC7_1_L01_P015" (solid, pour order 15): 25.216,38.1 24.962,37.846 24.962,33.782 25.216,33.528 28.62,33.528 28.772,33.68 28.772,37.77 28.442,38.1
GND on Top Layer "GND_L01_P008" (solid, remove dead copper, pour order 8): 47.22,27.298 47.22,23.798 45.52,22.098 44.395,22.098 44.395,26.448 45.245,27.298

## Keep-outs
Keep-Out Layer:
  lines w0.1: 49.549,4.464 49.549,7.964 50.972,7.964 50.972,4.464 49.549,4.464 ; 49.575,36.644 50.997,36.644 50.997,40.144 49.575,40.144 49.575,36.644 ; 49.676,30.761 49.676,32.661 51.099,32.661 51.099,30.761 49.676,30.761
  lines w0.2: 52.07,-0.127 0.07,-0.127 0.07,41.873 52.07,41.873 52.07,-0.127 ; 52.07,-0.127 52.07,-0.127 ; 52.07,-0.127 52.07,-0.127
  lines w0.8: 38.645,33.173 48.12,33.173 48.12,23.535
  lines w1: 43.42,6.298 46.57,6.298 46.57,13.198

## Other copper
Top Layer:
  rectangle net "VDC IN": 17.07,14.848 18.445,15.398
  region net Net_1: 5.139,15.091 5.139,16.142 cw(c5.62,16.142) 5.62,16.623 8.345,16.623 cw(c8.345,16.323) 8.645,16.323 8.645,15.085 cw(c8.133,15.085) 8.495,14.723 8.223,14.451 ccw(c9.45,13.223) 7.714,13.223 cw(c7.593,13.344) 7.593,13.173 5.454,13.173 cw(c5.454,13.6) 5.152,13.298
  region net Net_1: 5.683,15.544 5.597,15.544 ccw(c5.597,15.091) 5.143,15.091 5.143,5.606 cw(c5.002,5.606) 5.002,5.464 ccw(c5.002,5.336) 4.874,5.336 4.874,4.28 ccw(c5.883,4.28) 5.883,3.27 9.873,3.27 ccw(c9.873,3.583) 10.186,3.583 10.186,4.643 ccw(c9.558,4.643) 9.558,5.271 8.05,5.271 cw(c8.05,5.607) 7.714,5.607 7.714,14.939 ccw(c7.108,14.939) 7.108,15.546
  region net NetCX1_2: 4.095,28.448 6.926,31.279 cw(c8.722,29.483) 8.722,32.023 17.07,32.023 ccw(c17.07,32.523) 17.57,32.523 17.57,32.598 cw(c18.245,32.598) 18.245,33.273 18.495,33.273 cw(c18.495,32.523) 19.245,32.523 19.245,31.598 cw(c18.145,31.598) 18.145,30.498 8.9,30.498 ccw(c8.9,29.218) 7.995,30.123 5.675,27.803 cw(c5.12,28.358) 5.12,27.573 4.699,27.573 cw(c4.699,28.427) 4.095,27.823
  region net "VDC IN": 17.215,17.145 18.323,17.145 19.745,15.723 19.745,8.298 20.795,8.298 20.795,6.623 20.62,6.448 18.57,6.448 17.945,7.073 17.945,15.043
  region net "VDC IN": 28.22,21.123 28.541,21.444 31.395,21.444 31.72,21.119 31.72,19.198 29.72,17.198 27.02,14.498 27.02,16.623 28.22,17.823
  region net SR_VSS: 48.52,40.548 49.42,40.548 49.72,40.248 49.72,36.498 49.395,36.173 48.52,36.173 48.345,36.348 48.345,40.373
  region net SR_VSS: 51.02,40.473 51.92,40.473 52.22,40.173 52.22,36.423 51.895,36.098 51.02,36.098 50.845,36.273 50.845,40.298
  region net NetGPIO1_1: 48.345,33.498 48.895,34.048 49.695,33.248 49.695,30.573 49.52,30.398 48.545,30.398 48.345,30.598
  region net "VDC IN": 12.82,7.248 15.82,10.248 15.82,15.873 17.092,17.145 17.621,17.145 17.621,6.374 15.97,4.723 13.745,4.723 12.82,5.648
  region net "VDC IN": 20.62,6.448 22.489,6.448 22.995,6.954 22.995,8.248 22.345,8.898 22.345,11.373 22.995,12.023 22.12,12.898 21.745,12.898 20.007,11.16 20.007,8.163
Bottom Layer:
  rectangle net NetC24_2: 44.545,36.498 47.27,37.348
  rectangle net GND: 29.12,28.923 30.145,32.273
  rectangle net NetC14_1: 29.855,25.773 35.902,26.623
  region net GND: 5.594,10.341 5.283,10.341 ccw(c5.283,8.973) 3.915,8.973 3.295,8.973 cw(c3.295,10.198) 2.07,10.198 cw(c2.67,10.198) 2.67,10.798 4.845,10.798
  region net GND: 3.934,12.398 ccw(c4.684,12.398) 4.684,11.648 8.84,11.648 ccw(c8.84,13.223) 10.415,13.223 10.415,14.993 cw(c10.451,14.993) 10.451,15.029 11.776,15.029 ccw(c11.776,15.073) 11.82,15.073 cw(c11.82,14.972) 11.921,14.972 11.921,12.888 cw(c9.381,12.888) 9.381,10.348 4.02,10.348 cw(c4.02,11.873) 2.495,11.873
  region net Net_1: 5.182,16.066 5.182,13.261 ccw(c5.52,13.261) 5.52,12.923 7.045,12.923 ccw(c7.045,13.173) 7.295,13.173 7.295,14.448 cw(c7.645,14.448) 7.645,14.798 8.245,14.798 ccw(c8.245,15.13) 8.577,15.13 8.577,16.715 ccw(c8.495,16.715) 8.495,16.798 6.588,16.798 cw(c6.588,16.891) 6.495,16.891
  region net Net_1: 5.182,16.066 5.182,16.61 cw(c6.62,16.61) 6.62,18.048 13.267,18.048 cw(c13.267,14.855) 16.46,14.855 15.37,14.855 15.37,14.923 ccw(c13.72,14.923) 13.72,16.573 8.743,16.573 ccw(c8.743,16.374) 8.544,16.374 cw(c8.405,16.374) 8.405,16.235 7.52,16.235
  region net NetBD2_2: 10.259,22.645 10.259,23.182 cw(c10.547,23.182) 10.547,23.47 16.859,23.47 cw(c16.859,23.282) 17.047,23.282 17.047,21.458 cw(c16.878,21.458) 16.878,21.289 10.451,21.289 cw(c10.451,21.47) 10.27,21.47
  region net NetBD1_2: 0.563,23.361 7.067,23.361 cw(c6.879,23.172) 7.145,23.172 7.145,21.223 cw(c6.602,21.766) 6.602,20.998 1.02,20.998 cw(c1.02,21.68) 0.538,21.198 0.512,21.223 0.512,23.238 cw(c0.685,23.238)
  region net NetF1_2: 8.513,39.892 cw(c8.944,39.892) 8.944,40.323 9.788,40.323 cw(c9.788,39.852) 10.259,39.852 10.259,38.823 cw(c9.645,38.823) 10.079,38.389 ccw(c10.721,37.747) 9.813,37.747 9.813,35.223 ccw(c9.873,35.283) 9.873,35.198 10.084,35.198 ccw(c9.993,35.289) 10.121,35.289 10.121,37.06 cw(c10.776,37.06) 10.313,37.523 12.935,40.145 cw(c13.305,39.774) 13.305,40.298 14.295,40.298 cw(c13.857,38.429) 13.857,37.81 13.013,37.81 ccw(c13.013,36.03) 11.754,37.289 11.513,37.048 ccw(c12.479,36.082) 11.113,36.082 11.113,34.714 cw(c9.747,34.714) 10.713,33.748 cw(c10.2,34.261) 10.2,33.536 9.413,33.536 cw(c9.413,34.049) 9.05,33.686 8.913,33.823 cw(c9.879,34.789) 8.513,34.789
  region net NetLF1_4: 1.17,34.948 0.705,34.948 ccw(c0.705,34.454) 0.211,34.454 0.211,31.269 ccw(c0.913,31.269) 0.913,30.567 12.981,30.567 ccw(c12.981,31.813) 14.227,31.813 14.227,34.538 ccw(c13.997,34.538) 13.997,34.767 13.001,34.767 ccw(c13.001,34.473) 12.707,34.473 12.707,32.953 cw(c11.644,32.953) 11.644,31.889 6.861,31.889 cw(c6.861,34.429) 5.065,32.633 3.086,34.612 ccw(c2.313,33.839) 2.313,34.933
  region net GND: 12.917,14.343 12.886,14.458 ccw(c12.807,14.029) 12.379,14.108 12.379,10.288 ccw(c12.789,10.288) 12.598,9.925 13.961,8.706 ccw(c13.788,9.355) 14.369,9.019 14.744,9.393 13.248,11.087 13.241,13.147
  region net NetCX1_1: 12.901,28.848 ccw(c12.9,27.975) 12.282,28.592 ccw(c12.418,28.456) 12.226,28.456 12.226,26.984 ccw(c13.514,28.029) 13.028,26.443 14.487,26.448 17.656,26.457 ccw(c17.652,27.906) 18.676,26.881 22.202,30.407 ccw(c21.164,31.445) 22.632,31.446 22.632,38.208 ccw(c20.213,38.208) 21.923,39.92 21.62,40.223 ccw(c20.423,39.027) 20.422,40.719 19.151,40.719 ccw(c19.89,39.98) 18.845,39.98 18.845,37.819 19.798,37.819 cw(c19.798,36.76) 20.547,37.509 cw(c19.182,36.142) 21.114,36.142 21.114,32.419 cw(c18.575,32.418) 20.37,30.623 19.27,29.523 cw(c17.641,31.152) 17.64,28.848
  region net NetGPIO1_1: 48.52,30.698 48.52,30.198 48.77,29.948 51.645,29.948 51.97,30.273 51.97,30.618 48.885,30.618 48.82,30.683
  region net NetGPIO1_1: 48.52,32.744 48.52,33.398 48.795,33.673 51.72,33.673 51.957,33.436 51.957,33.098 51.732,32.873 49.37,32.873
  region net NetGPIO1_1: 46.545,38.245 46.545,40.573 46.745,40.773 47.595,40.773 47.795,40.573 47.795,38.286 47.67,38.161 46.63,38.161
  region net SR_VSS: 51.095,35.923 51.095,40.373 51.195,40.473 51.92,40.473 51.995,40.398 51.995,35.898 51.895,35.798 51.22,35.798
  region net SR_VSS: 48.395,40.423 48.47,40.498 49.445,40.498 49.545,40.398 49.545,36.323 49.395,36.173 48.545,36.173 48.395,36.323
  region net NetF1_2: 14.02,40.296 14.36,40.296 14.495,40.16 14.495,37.91 14.37,37.785 13.883,37.785 13.07,38.598 13.07,38.767
  region net NetD8_1: 25.545,23.732 25.97,24.157 25.97,26.698 26.682,26.698 26.795,26.585 26.795,22.748 26.67,22.623 25.545,22.623
  region net NetC19_1: 36.27,33.873 36.97,33.173 36.97,33.498 37.37,33.898
  region net GND: 32.82,29.573 37.71,29.533 38.42,30.565 38.604,30.748 39.295,30.748 39.645,30.398 39.645,29.273 40.12,28.798 41.583,28.798 41.82,28.56 41.82,27.798 41.77,27.748 32.795,27.748 32.595,27.948 32.595,29.348
  region net NetR13_1: 25.495,18.627 25.495,20.723 25.595,20.823 26.72,20.823 26.82,20.723 26.82,16.916 26.225,16.321 24.858,16.321 24.545,16.634 24.545,17.677
  region net NetC16_1: 41.585,27.083 43.245,25.423 43.245,24.423 42.741,24.423 42.72,24.402 42.72,24.823 41.685,25.858
  region net NetC16_1: 37.101,27.098 41.57,27.098 41.745,26.923 41.745,25.948 41.67,25.873 37.195,25.873 37.07,25.998 37.07,27.067
  region net GND: 17.47,3.305 17.47,0.298 20.22,0.298 20.22,3.623 19.245,4.598 17.795,4.598 17.77,4.623
  region net GND: 21.109,17.409 21.923,17.409 23.03,16.79 23.03,15.402 21.077,14.198 20.297,14.198 20.297,16.597
  region net SR_VSS: 46.867,1.124 45.642,1.512 46.867,1.899
  region net SR_VSS: 46.867,1.524 45.642,1.912 46.867,2.299
  region net GND: 37.613,1.987 38.838,1.599 37.613,1.212
  region net GND: 37.588,2.624 38.813,2.237 37.588,1.849
  region net NetC24_1: 44.795,40.798 45.27,40.323 45.27,38.448 44.995,38.173 44.245,38.173 44.007,38.41 44.007,40.798
  region net GND: 19.995,3.848 21.02,2.823 34.525,2.823 34.945,2.403 34.945,0.923 34.32,0.298 20.22,0.298 19.395,2.173 19.645,3.848
  region net NetC2_2: 39.455,24.232 40.02,23.667 40.02,22.498 39.82,22.298 28.564,22.298 28.564,24.223 28.573,24.232
  region net NetF1_1: 0.736,40.373 4.586,40.373 5.011,39.948 5.011,38.473 4.711,38.173 0.861,38.173 0.586,38.448 0.586,40.223
  region net NetCX1_1: 19.445,40.748 19.795,40.398 19.795,38.273 19.42,37.898 17.92,37.898 17.395,38.423 17.395,40.573 17.57,40.748
  region net NetCX1_2: 18.639,34.523 18.97,34.192 18.97,31.786 18.807,31.623 17.782,31.623 17.376,32.029 17.376,34.154 17.745,34.523
  region net NetF1_2: 14.295,40.298 15.52,39.91 14.295,39.523
  region net NetF1_2: 14.295,38.767 15.52,38.379 14.295,37.992
  region net NetF1_2: 14.295,39.535 15.52,39.148 14.295,38.76
  region net NetCX1_1: 17.107,39.504 15.882,39.892 17.107,40.279
  region net NetCX1_1: 17.107,38.717 15.882,39.104 17.107,39.492
  region net NetCX1_1: 17.107,37.954 15.882,38.342 17.107,38.729
  region net NetCX1_1: 17.57,40.748 17.07,40.248 17.07,37.898 17.17,37.798 19.695,37.798 19.795,37.898 19.795,40.398 19.445,40.748
  region net NetCX1_2: 17.182,32.129 15.957,32.517 17.182,32.904
  region net NetCX1_2: 17.182,32.892 15.957,33.279 17.182,33.667
  region net NetCX1_2: 17.182,33.679 15.957,34.067 17.182,34.454
  region net NetLF1_4: 14.37,33.71 15.595,33.323 14.37,32.935
  region net NetLF1_4: 14.37,32.942 15.595,32.554 14.37,32.167
  region net NetLF1_4: 14.37,34.473 15.595,34.085 14.37,33.698
  region net NetLF1_4: 13.995,34.473 14.483,34.473 14.583,34.373 14.583,32.21 14.42,32.048 13.92,32.048
  region net NetCX1_2: 17.62,32.029 17.283,32.029 17.032,32.279 17.032,34.292 17.195,34.454 17.695,34.454
  region net NetBD1_2: 0.563,23.361 0.951,24.586 1.338,23.361
  region net NetBD1_2: 1.326,23.361 1.713,24.586 2.101,23.361
  region net NetCX1_2: 1.372,26.289 0.984,25.064 0.597,26.289
  region net NetCX1_2: 2.134,26.289 1.746,25.064 1.359,26.289
  region net NetBD2_2: 16.216,23.448 16.603,24.673 16.991,23.448
  region net NetBD2_2: 15.447,23.448 15.834,24.673 16.222,23.448
  region net NetCX1_1: 16.213,26.457 15.825,25.232 15.438,26.457
  region net NetCX1_1: 16.975,26.457 16.588,25.232 16.2,26.457
  region net GND: 37.753,3.031 38.103,2.681 38.103,0.981 37.828,0.706 36.478,0.706 36.128,1.056 36.128,2.831 36.328,3.031
  region net SR_VSS: 47.936,3.256 48.286,2.906 48.286,1.206 48.011,0.931 46.661,0.931 46.311,1.281 46.311,2.668 46.898,3.256
  region net NetR35_1: 35.92,40.848 37.27,40.848 37.27,38.998 36.39,38.118 35.82,38.688 35.82,40.748
  region net NetC19_1: 35.795,36.898 37.045,36.898 37.37,36.573 37.37,33.898 37.345,33.873 36.27,33.873 35.795,34.348
  region net SR_VSS: 44.795,35.698 44.97,35.523 44.97,34.323 44.708,34.061 44.133,34.061 43.87,34.323 43.87,35.498 44.07,35.698
  region net "VDC IN": 20.72,8.673 22.481,8.673 23.245,7.909 23.245,6.473 23.245,4.788 23.03,4.573 21.395,4.573 21.395,5.848 20.32,6.923 20.32,8.273
  region net NetD2_1: 19.92,22.723 19.92,25.23 21.338,26.648 21.62,26.648 22.67,25.598 22.67,25.098 21.82,24.248 21.82,22.773 21.595,22.548
  region net NetR7_1: 23.03,17.627 21.737,18.673 19.945,18.673 19.845,18.773 19.845,20.339 19.92,20.414 21.954,20.414 22.07,20.298 22.07,19.748 22.27,19.548 23.57,19.548 24.082,19.035 24.082,18.11 23.599,17.627
  region net NetR13_1: 23.618,21.448 26.82,21.448 26.995,21.273 26.995,17.091 26.82,16.916 26.655,16.916 25.495,18.076 25.495,19.773 25.12,20.148 23.545,20.148 23.445,20.248 23.445,21.275
  region net GND: 33.721,29.524 34.37,30.173 34.37,32.198 34.47,32.298 36.07,32.298 36.445,31.923 36.445,30.273 37.27,29.448 35.626,29.448 35.375,29.197
  region net NetC7_1: 23.32,28.609 24.934,30.223 26.17,30.223 26.17,28.483 25.995,28.308 25.53,28.308 24.845,27.623 23.322,27.623 23.32,27.625

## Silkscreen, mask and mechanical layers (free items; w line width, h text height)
Top Overlay:
  lines w0.1: 49.97,39.998 50.77,39.998 ; 21.294,11.813 21.294,11.813
  lines w0.15: 49.97,39.998 49.97,3.623 50.77,3.623 50.77,39.998
  text "L" at 1.195,40.623 h0.8
  text "N" at 0.451,30.658 h0.8
Bottom Overlay:
  drawing of 17 lines, arcs and shapes, not listed
  text "PAG1 GaN 65WREV1.0" at 15.996,6.248 h1
  text "2020/12/12" at 8.731,0.762 h1
Top Solder:
  lines w0.254: 28.67,38.278 33.827,38.278 ; 29.204,37.744 33.827,37.744 ; 29.636,37.211 33.827,37.211
Bottom Solder:
  lines w0.254: 28.696,38.303 31.464,38.303 ; 29.382,33.604 30.525,33.604 31.541,32.588 ; 29.89,38.989 33.573,38.989 ; 29.89,39.548 33.573,39.522 ; 29.94,40.081 33.598,40.056 ; 31.083,33.757 32.099,32.741 ; 31.744,27.61 31.744,29.87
